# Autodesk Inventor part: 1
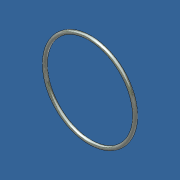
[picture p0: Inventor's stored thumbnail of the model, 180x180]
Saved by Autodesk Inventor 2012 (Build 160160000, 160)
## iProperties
Created: 2013-04
Part Number: 1
Material: Steel
Document SubType Name: Modeling
Designer: Admin
Density: 7.85 g/cm^3
Mass: 30.6807 g
Surface Area: 39.0836 cm^2
Volume: 3.90836 cm^3
Author: Admin
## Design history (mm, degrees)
node "11"
node "1"
node "Base1"
